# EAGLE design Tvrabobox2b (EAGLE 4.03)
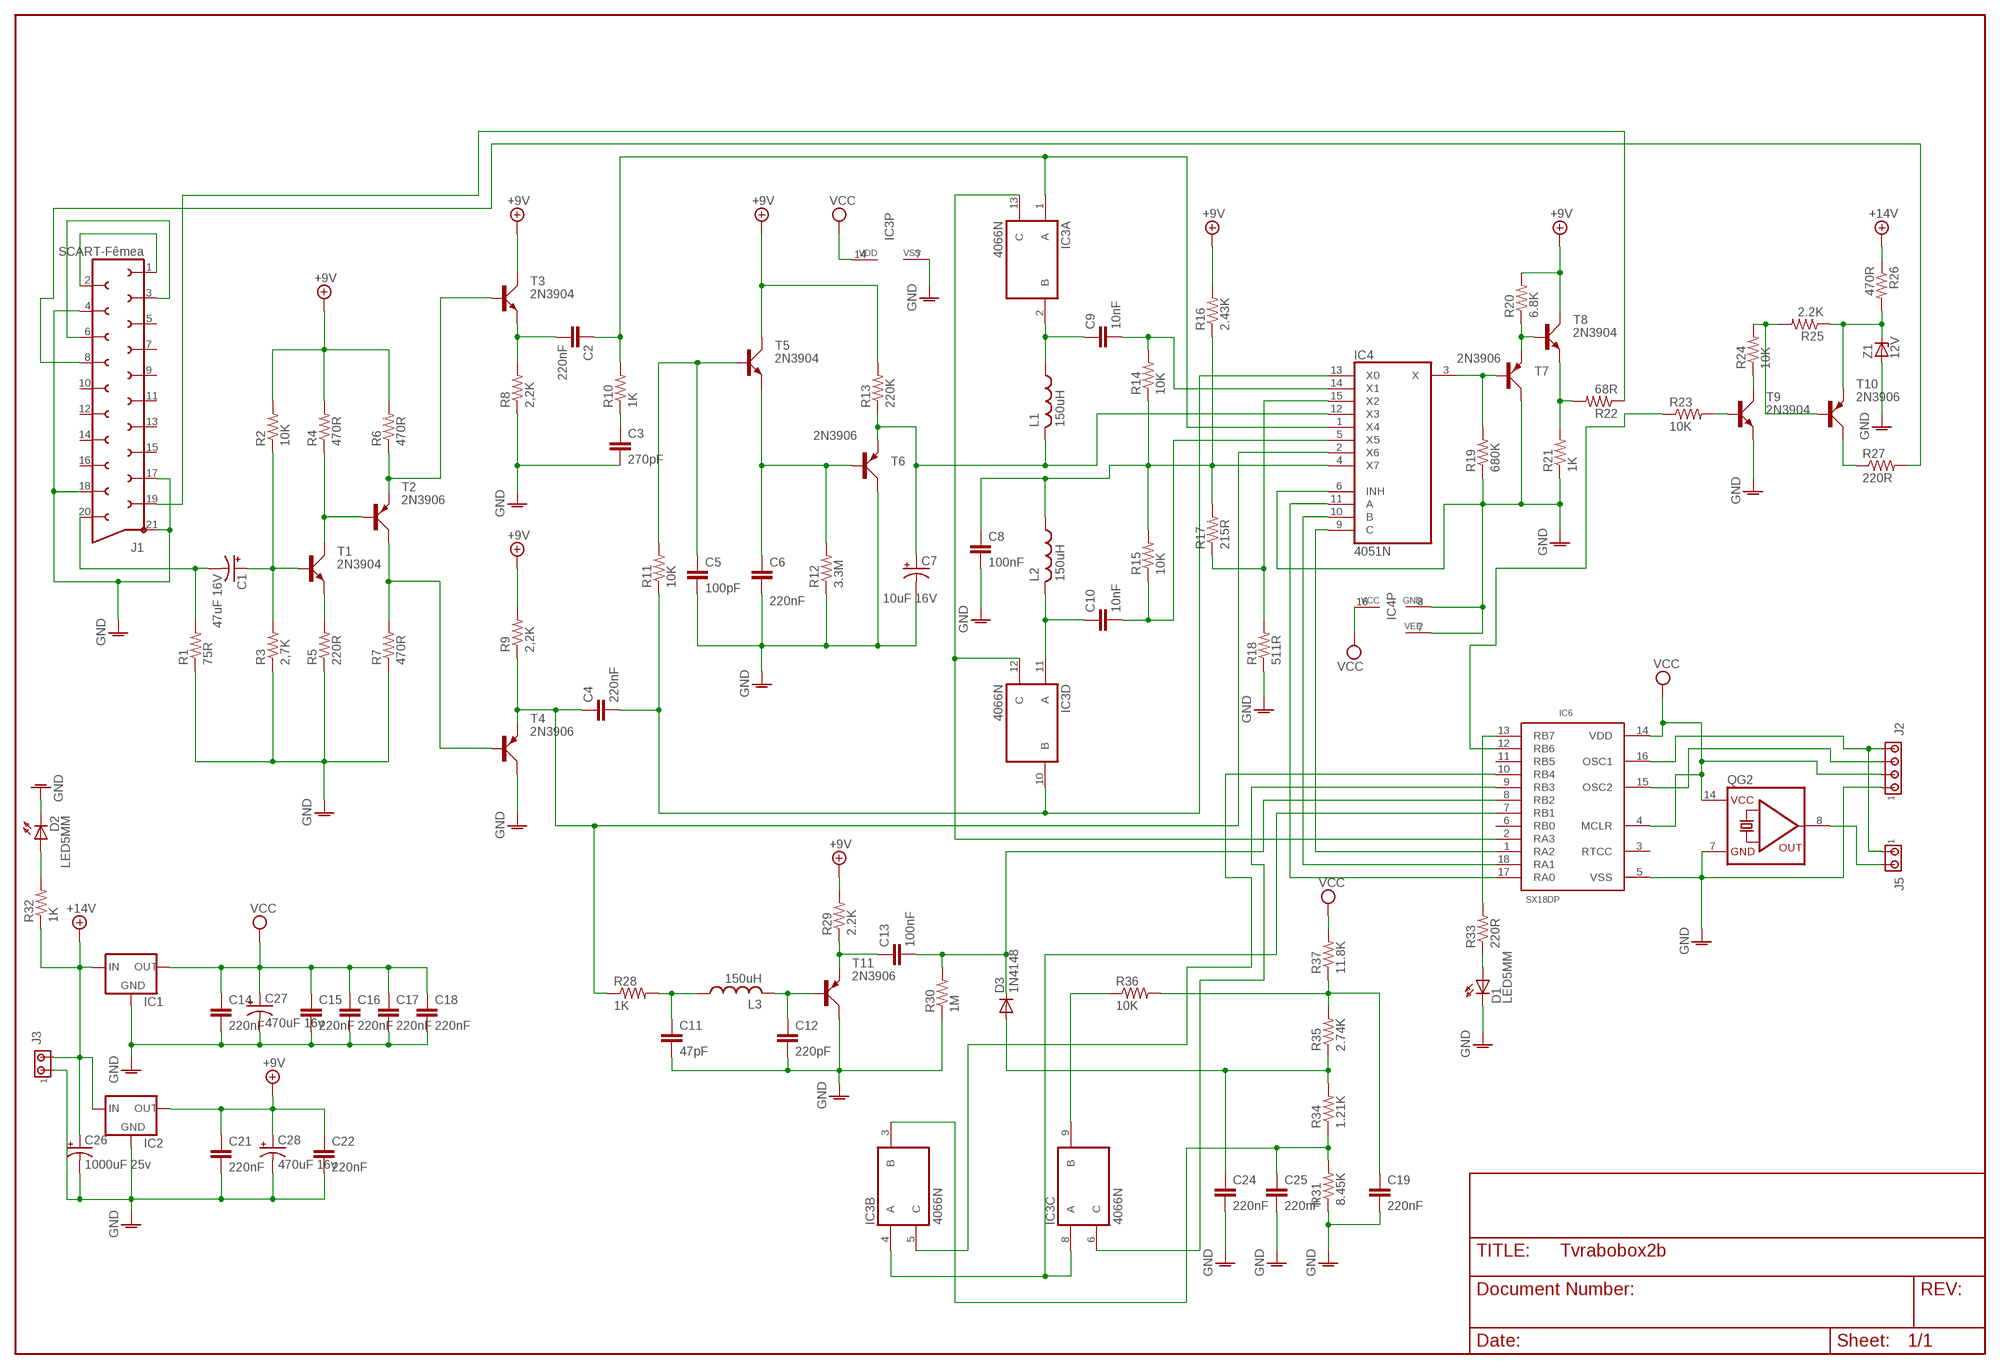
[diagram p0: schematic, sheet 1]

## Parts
C1  47uF 16V  CPOL-USTT2D5  [TT2D5]
C2  220nF  C-EU050-050X075  [C050-050X075]
C3  270pF  C-EU025-025X050  [C025-025X050]
C4  220nF  C-EU050-050X075  [C050-050X075]
C5  100pF  C-EU025-025X050  [C025-025X050]
C6  220nF  C-EU050-050X075  [C050-050X075]
C7  10uF 16V  CPOL-USTT2D5  [TT2D5]
C8  100nF  C-EU025-025X050  [C025-025X050]
C9  10nF  C-EU025-025X050  [C025-025X050]
C10  10nF  C-EU025-025X050  [C025-025X050]
C11  47pF  C-EU025-025X050  [C025-025X050]
C12  220pF  C-EU025-025X050  [C025-025X050]
C13  100nF  C-EU025-025X050  [C025-025X050]
C14  220nF  C-EU050-050X075  [C050-050X075]
C15  220nF  C-EU050-050X075  [C050-050X075]
C16  220nF  C-EU050-050X075  [C050-050X075]
C17  220nF  C-EU050-050X075  [C050-050X075]
C18  220nF  C-EU050-050X075  [C050-050X075]
C19  220nF  C-EU050-050X075  [C050-050X075]
C21  220nF  C-EU050-050X075  [C050-050X075]
C22  220nF  C-EU050-050X075  [C050-050X075]
C24  220nF  C-EU050-050X075  [C050-050X075]
C25  220nF  C-EU050-050X075  [C050-050X075]
C26  1000uF 25v  CPOL-USTT5D10  [TT5D10]
C27  470uF 16v  CPOL-USTT2D7  [TT2D7]
C28  470uF 16v  CPOL-USTT2D7  [TT2D7]
D1  LED5MM  [LED5MM]
D2  LED5MM  [LED5MM]
D3  1N4148  [DO35-10]
IC1  78XXS  [78XXS]
IC2  78XXS  [78XXS]
IC3  4066N  [DIL14]
IC4  4051N  [DIL16]
IC6  SX18AC/DP  [18DIP]
J1  SCART-Fêmea  SCART-F  [SCART-F]
J2  MTA04-100  [10X04MTA]
J3  MTA02-156  [1X2MTA]
J5  MTA02-100  [10X02MTA]
L1  150uH  L-US0207/10  [0207/10]
L2  150uH  L-US0207/10  [0207/10]
L3  150uH  L-US0207/10  [0207/10]
QG2  QG5860  [DIL14S]
R1  75R  R-US_0207/10  [0207/10]
R2  10K  R-US_0207/10  [0207/10]
R3  2,7K  R-US_0207/10  [0207/10]
R4  470R  R-US_0207/10  [0207/10]
R5  220R  R-US_0207/10  [0207/10]
R6  470R  R-US_0207/10  [0207/10]
R7  470R  R-US_0207/10  [0207/10]
R8  2,2K  R-US_0207/10  [0207/10]
R9  2,2K  R-US_0207/10  [0207/10]
R10  1K  R-US_0207/10  [0207/10]
R11  10K  R-US_0207/10  [0207/10]
R12  3.3M  R-US_0207/10  [0207/10]
R13  220K  R-US_0207/10  [0207/10]
R14  10K  R-US_0207/10  [0207/10]
R15  10K  R-US_0207/10  [0207/10]
R16  2.43K  R-US_0207/10  [0207/10]
R17  215R  R-US_0207/10  [0207/10]
R18  511R  R-US_0207/10  [0207/10]
R19  680K  R-US_0207/10  [0207/10]
R20  6.8K  R-US_0207/10  [0207/10]
R21  1K  R-US_0207/10  [0207/10]
R22  68R  R-US_0207/10  [0207/10]
R23  10K  R-US_0207/10  [0207/10]
R24  10K  R-US_0207/10  [0207/10]
R25  2.2K  R-US_0207/10  [0207/10]
R26  470R  R-US_0207/10  [0207/10]
R27  220R  R-US_0207/10  [0207/10]
R28  1K  R-US_0207/10  [0207/10]
R29  2.2K  R-US_0207/10  [0207/10]
R30  1M  R-US_0207/10  [0207/10]
R31  8.45K  R-US_0207/10  [0207/10]
R32  1K  R-US_0207/10  [0207/10]
R33  220R  R-US_0207/10  [0207/10]
R34  1.21K  R-US_0207/10  [0207/10]
R35  2.74K  R-US_0207/10  [0207/10]
R36  10K  R-US_0207/10  [0207/10]
R37  11.8K  R-US_0207/10  [0207/10]
T1  2N3904  [TO92D]
T2  2N3906  [TO92D]
T3  2N3904  [TO92D]
T4  2N3906  [TO92D]
T5  2N3904  [TO92D]
T6  2N3906  [TO92D]
T7  2N3906  [TO92D]
T8  2N3904  [TO92D]
T9  2N3904  [TO92D]
T10  2N3906  [TO92D]
T11  2N3906  [TO92D]
Z1  12V  BZX55  [DO35Z10]

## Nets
+9V: C21.2 C22.2 C28.+ IC2.OUT R2.2 R4.2 R6.2 R9.2 R13.2 R16.2 R20.2 R29.2 T3.C T5.C T8.C
+14V: C26.+ IC1.IN IC2.IN J3.2 R26.1 R32.1
GNDA: C3.1 C5.1 C6.1 C7.- C8.1 C11.1 C12.1 C14.1 C15.1 C16.1 C17.1 C18.1 C19.1 C21.1 C22.1 C24.1 C25.1 C26.- C27.- C28.- D1.K(C) D2.K(C) IC1.GND IC2.GND IC3.7(P:VSS) IC4.6(INH) IC4.7(VEE) IC4.8(GND) IC6.5(VSS) J1.4 J1.17 J1.18 J1.21 J2.4 J3.1 QG2.7(GND) R1.1 R3.1 R5.1 R7.1 R8.1 R12.1 R18.1 R19.1 R21.1 R30.1 R31.1 T4.C T6.C T7.C T9.E T11.C Z1.A ; supply symbol labelled GND
N$1: J1.1 J1.2
N$2: J1.3 J1.6
N$3: C4.1 IC3.10(D:B) IC4.13(X0) R11.1
N$4: C3.2 R10.1
N$5: R4.1 T1.C T2.B
N$6: R5.2 T1.E
N$7: C1.+ R2.1 R3.2 T1.B
N$8: C1.- J1.20 R1.2
N$9: C2.1 R8.2 T3.E
N$10: C4.2 IC4.2(X6) R9.1 R28.1 T4.E
N$11: C9.2 IC3.2(A:B) L1.2
N$12: C2.2 IC3.1(A:A) IC4.1(X4) R10.2
N$13: R6.1 T2.E T3.B
N$14: R7.2 T2.C T4.B
N$15: C5.2 R11.2 T5.B
N$16: C6.2 R12.2 T5.E T6.B
N$17: C8.2 IC4.4(X7) L2.2 R14.1 R15.2 R16.1 R17.2
N$18: IC4.15(X2) R17.1 R18.2
N$19: C7.+ IC4.12(X3) L1.1 R13.1 T6.E
N$20: C9.1 IC4.14(X1) R14.2
N$21: IC4.11(A) IC6.17(RA0)
N$22: C10.2 IC3.11(D:A) L2.1
N$23: IC4.10(B) IC6.18(RA1)
N$24: C10.1 IC4.5(X5) R15.1
N$25: IC4.9(C) IC6.1(RA2)
N$26: IC3.12(D:C) IC3.13(A:C) IC6.2(RA3)
N$27: IC4.3(X) R19.2 T7.B
N$28: R20.1 T7.E T8.B
N$29: J1.19 R22.1
N$30: R23.2 T9.B
N$31: R21.2 R22.2 T8.E
N$32: R24.1 T9.C
N$33: R24.2 R25.2 T10.B
N$34: C24.2 D3.A R34.2 R35.1
N$35: R27.1 T10.C
N$36: IC6.12(RB6) R23.1
N$37: J1.8 R27.2
N$38: R25.1 R26.2 T10.E Z1.C
N$39: IC3.9(C:B) R36.1
N$40: C25.2 IC3.3(B:B) R31.2 R34.1
N$41: IC3.6(C:C) IC6.9(RB3)
N$42: C11.2 L3.2 R28.2
N$43: C12.2 L3.1 T11.B
N$44: C13.2 R29.1 T11.E
N$45: IC3.5(B:C) IC6.10(RB4)
N$46: C13.1 D3.C IC6.8(RB2) R30.2
N$47: D2.A R32.2
N$48: IC3.4(B:A) IC3.8(C:A) IC6.7(RB1)
N$49: C19.2 R35.2 R36.2 R37.1
N$52: IC6.15(OSC2) J2.2
N$53: IC6.16(OSC1) J2.1 J5.1
N$55: J5.2 QG2.8(OUT)
N$63: D1.A R33.1
N$64: IC6.13(RB7) R33.2
VCC: C14.2 C15.2 C16.2 C17.2 C18.2 C27.+ IC1.OUT IC3.14(P:VDD) IC4.16(VCC) IC6.4(MCLR) IC6.14(VDD) J2.3 QG2.14(VCC) R37.2
Unconnected: IC6.3(RTCC) IC6.6(RB0) IC6.11(RB5) J1.5 J1.7 J1.9 J1.10 J1.11 J1.12 J1.13 J1.14 J1.15 J1.16

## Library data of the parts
C1 C7 C26-C28 = rcl:CPOL-US: POLARIZED CAPACITOR, American symbol
C2-C6 C8-C19 C21 C22 C24 C25 = rcl:C-EU: CAPACITOR, European symbol
D1 D2 = led:LED5MM: LED
D3 = diode:1N4148: DIODE
IC1 IC2 = v-reg:78XXS: VOLTAGE REGULATOR
IC3 = 40xx:4066: Quad bilateral ANALOG SWITCH
IC4 = 40xx:4051: 8-channel ANALOG MULTIPLEXER
IC6 = ubicom_v2:SX18AC/DP
J1 = con-hirschmann:SCART-F: TV SCART CONNECTOR
J2 = con-amp:MTA04-100: AMP CONNECTOR
J3 = con-amp:MTA02-156: AMP CONNECTOR
J5 = con-amp:MTA02-100: AMP CONNECTOR
L1-L3 = rcl:L-US: INDUCTOR, American symbol
QG2 = crystal:QG5860: CRYSTAL RESONATOR
R1-R37 = rcl:R-US_: RESISTOR, American symbol
T1 T3 T5 T8 T9 = transistor-small-signal:2N3904: NPN TRANSISTOR
T2 T4 T6 T7 T10 T11 = transistor-small-signal:2N3906: PNP TRANSISTOR
Z1 = diode:BZX55: Z DIODE

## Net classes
0 default: width 0.4 mm

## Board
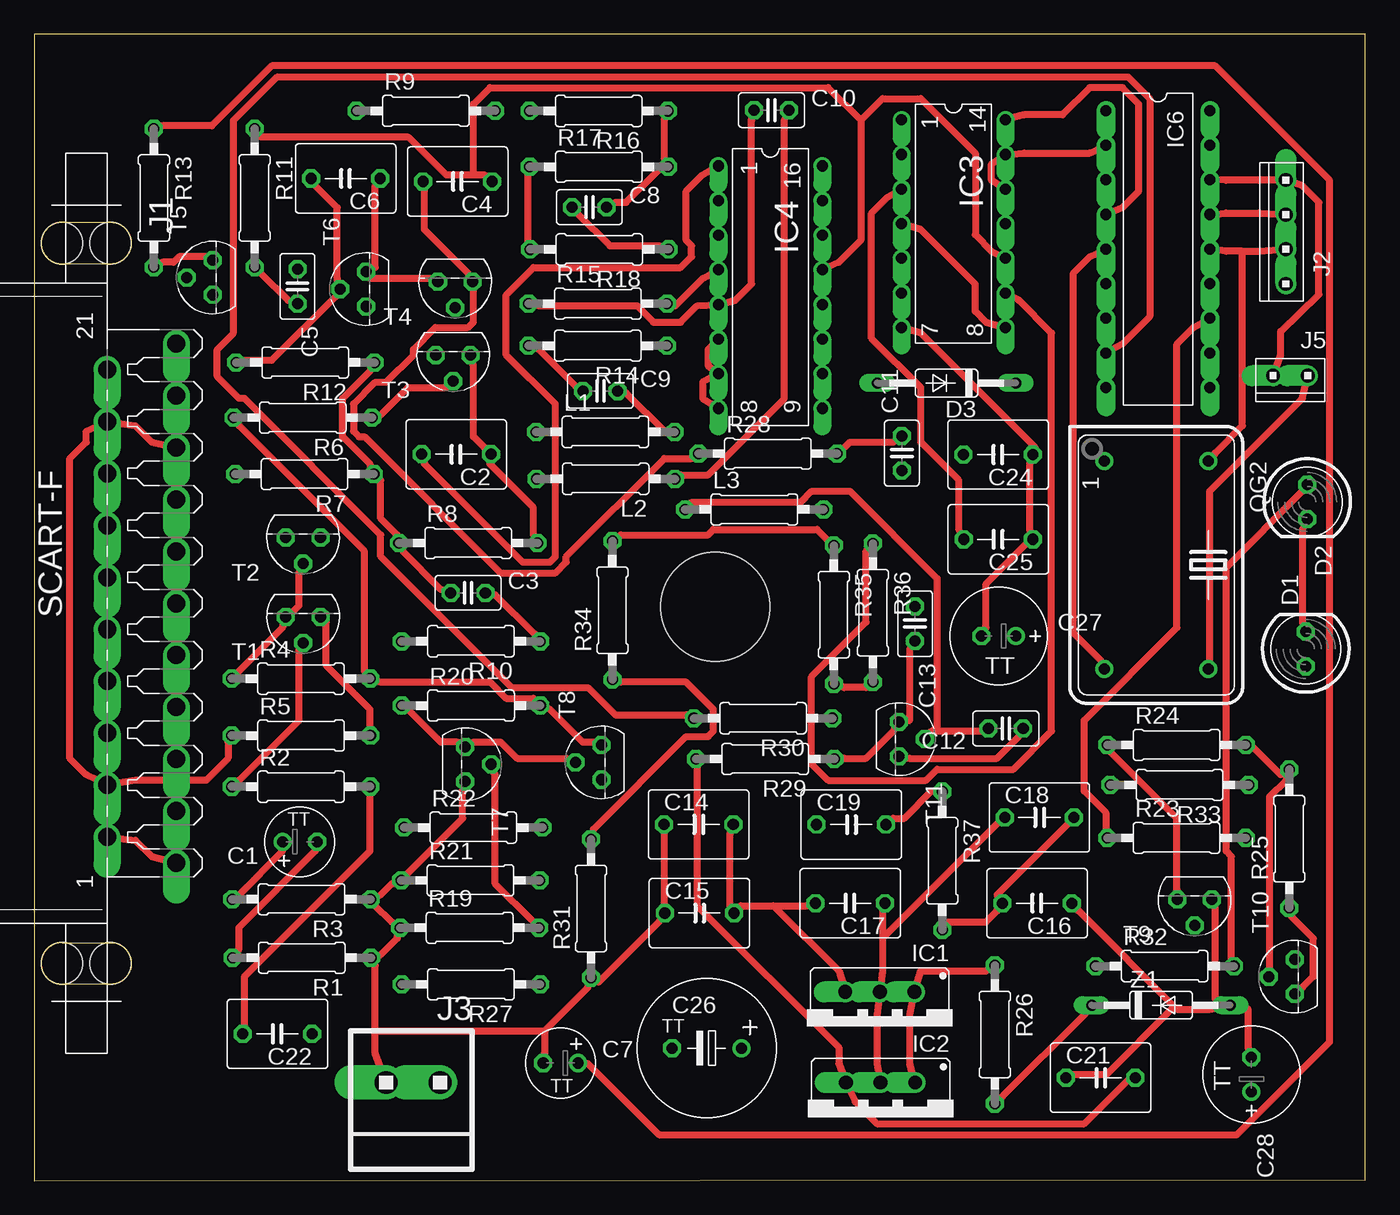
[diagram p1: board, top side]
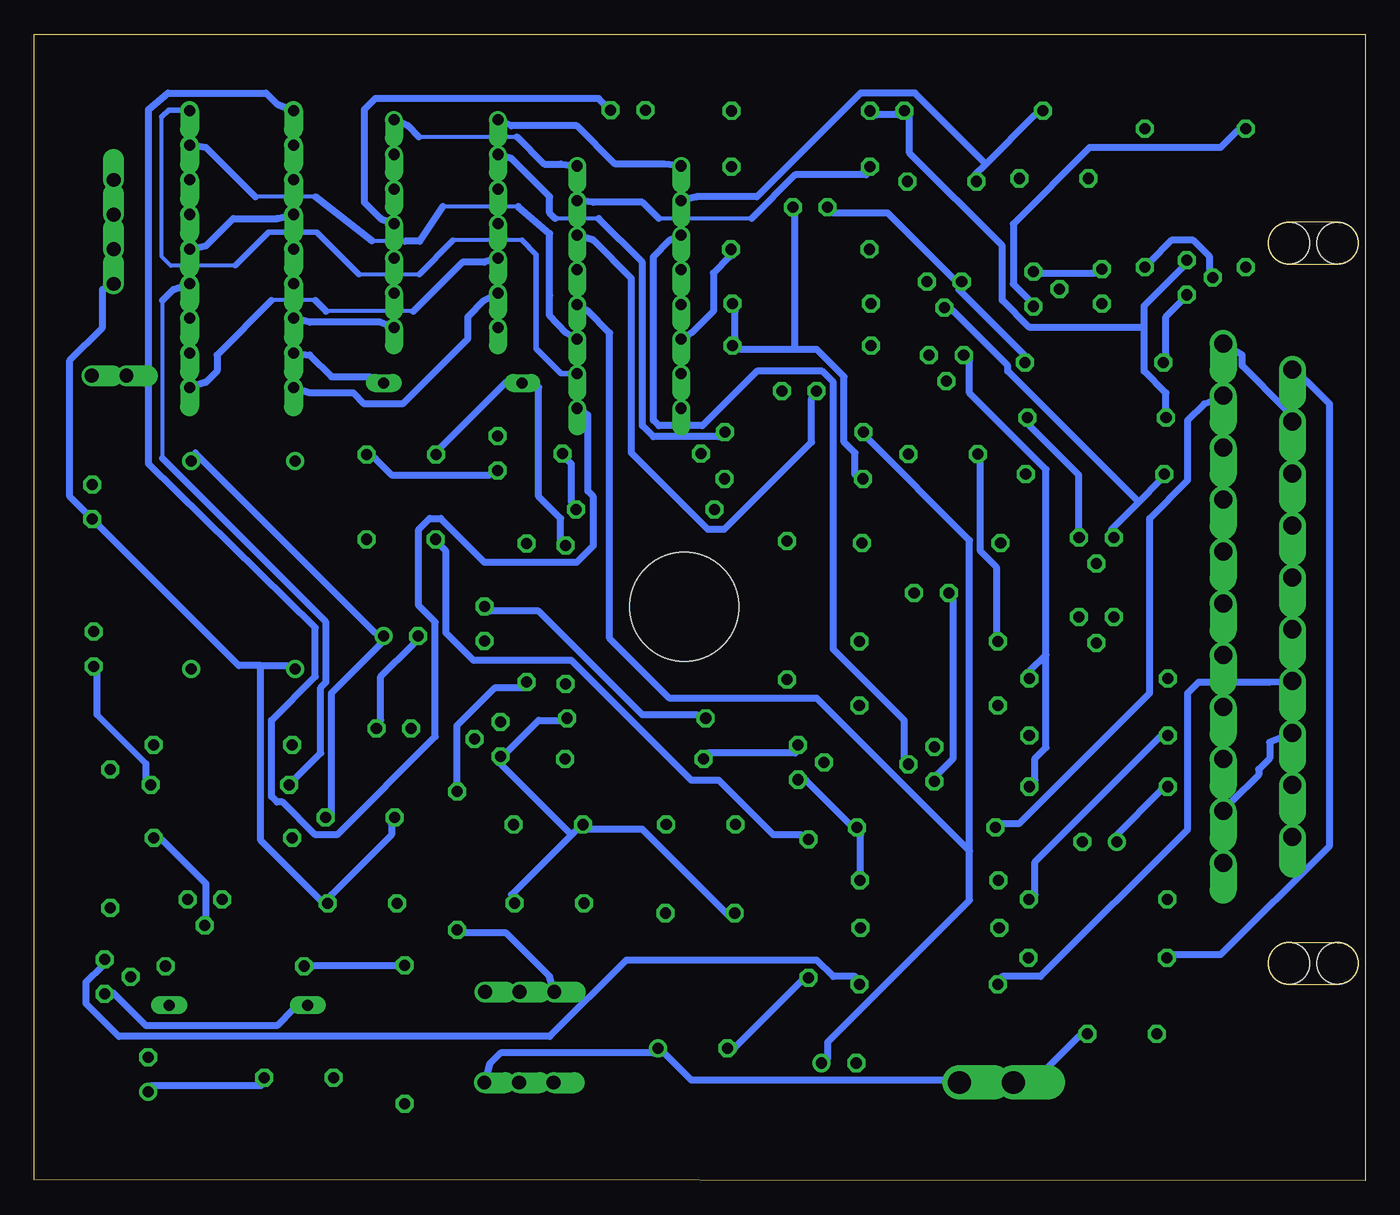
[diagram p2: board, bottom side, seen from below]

Size 97.65 x 84.11 mm. Coordinates in mm from the lower left corner, seen from the top.
Outline: 0,0 97.65,0.06 97.65,84.11 0,84.11 0,0
Copper layers used: Top, Bottom
Holes 8 mm at 49.98,42.12

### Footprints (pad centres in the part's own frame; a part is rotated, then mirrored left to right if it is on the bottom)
TT2D5 = drill 0.813 round: + 1.27,0 | drill 0.813 octagon: - -1.27,0
C050-050X075 = drill 0.813 octagon: 1 -2.54,0; 2 2.54,0
C025-025X050 = drill 0.813 octagon: 1 -1.27,0; 2 1.27,0
TT5D10 = drill 0.813 round: + 2.54,0 | drill 0.813 octagon: - -2.54,0
TT2D7 = drill 0.813 round: + 1.27,0 | drill 0.813 octagon: - -1.27,0
LED5MM = drill 0.813 octagon: A -1.27,0; K 1.27,0
DO35-10 = drill 0.813 long: A 5.08,0; C -5.08,0
78XXS = drill 1.016 offset: GND 0,-2.54; IN -2.54,-2.54; OUT 2.54,-2.54
DIL14 = drill 0.813 offset: 1 -7.62,-3.81; 2 -5.08,-3.81; 3 -2.54,-3.81; 4 0,-3.81; 5 2.54,-3.81; 6 5.08,-3.81; 7 7.62,-3.81; 8 7.62,3.81; 9 5.08,3.81; 10 2.54,3.81; 11 0,3.81; 12 -2.54,3.81; 13 -5.08,3.81; 14 -7.62,3.81
DIL16 = drill 0.813 offset: 1 -8.89,-3.81; 2 -6.35,-3.81; 3 -3.81,-3.81; 4 -1.27,-3.81; 5 1.27,-3.81; 6 3.81,-3.81; 7 6.35,-3.81; 8 8.89,-3.81; 9 8.89,3.81; 10 6.35,3.81; 11 3.81,3.81; 12 1.27,3.81; 13 -1.27,3.81; 14 -3.81,3.81; 15 -6.35,3.81; 16 -8.89,3.81
18DIP = drill 0.813 pad 1.397 offset: 1 -16.192,-3.81; 2 -13.652,-3.81; 3 -11.113,-3.81; 4 -8.572,-3.81; 5 -6.032,-3.81; 6 -3.493,-3.81; 7 -0.953,-3.81; 8 1.587,-3.81; 9 4.128,-3.81; 10 4.128,3.81; 11 1.587,3.81; 12 -0.953,3.81; 13 -3.493,3.81; 14 -6.032,3.81; 15 -8.572,3.81; 16 -11.113,3.81; 17 -13.652,3.81; 18 -16.192,3.81
SCART-F = drill 1.321 offset: 1 19.05,5.08; 2 17.145,0; 3 15.24,5.08; 4 13.335,0; 5 11.43,5.08; 6 9.525,0; 7 7.62,5.08; 8 5.715,0; 9 3.81,5.08; 10 1.905,0; 11 0,5.08; 12 -1.905,0; 13 -3.81,5.08; 14 -5.715,0; 15 -7.62,5.08; 16 -9.525,0; 17 -11.43,5.08; 18 -13.335,0; 19 -15.24,5.08; 20 -17.145,0; 21 -19.05,5.08 | hole 3.023: 26.416,0.254; 26.416,-3.302; -26.416,0.254; -26.416,-3.302
10X04MTA = drill 1.016 offset: 1 3.81,0; 2 1.27,0; 3 -1.27,0; 4 -3.81,0
1X2MTA = drill 1.676 offset: 1 1.981,0; 2 -1.981,0
10X02MTA = drill 1.016 offset: 1 1.27,0; 2 -1.27,0
0207/10 = drill 0.813 octagon: 1 -5.08,0; 2 5.08,0
DIL14S = drill 0.813 round: 1 -7.62,-3.81; 7 7.62,-3.81; 8 7.62,3.81; 14 -7.62,3.81
TO92D = drill 0.813 octagon: B 0,1.905; C 1.27,0; E -1.27,0
DO35Z10 = drill 0.813 long: A 5.08,0; C -5.08,0

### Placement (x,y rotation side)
C1  19.49,24.87 180 top
C2  30.97,53.29 180 top
C3  31.83,43.13 0 top
C4  31.06,73.3 180 top
C5  19.32,65.61 270 top
C6  22.85,73.53 180 top
C7  38.62,8.64 0 top
C8  40.73,71.41 0 top
C9  41.53,57.94 0 top
C10  54.08,78.53 0 top
C11  63.65,53.37 90 top
C12  71.27,33.18 180 top
C13  64.61,40.87 270 top
C14  48.74,26.14 0 top
C15  48.8,19.64 0 top
C16  73.57,20.36 180 top
C17  59.87,20.37 180 top
C18  73.74,26.65 0 top
C19  59.94,26.13 0 top
C21  78.22,7.57 0 top
C22  17.85,10.78 180 top
C24  70.71,53.27 180 top
C25  70.72,47.05 180 top
C26  49.33,9.73 0 top
C27  70.76,39.96 0 top
C28  89.29,7.8 270 top
D1  93.28,39.01 90 top
D2  93.38,49.8 270 top
D3  66.93,58.51 180 top
IC1  62.03,11.31 180 top
IC2  62.08,4.66 180 top
IC3  67.43,70.2 270 top
IC4  54.01,65.55 270 top
IC6  82.43,62.31 270 top
J1  5.36,42.36 270 top
J2  91.82,69.6 90 top
J3  27.79,7.21 180 top
J5  92.14,59.06 180 top
L1  41.91,54.94 0 top
L2  41.93,51.49 180 top
L3  52.83,49.25 0 top
QG2  82.31,45.17 270 top
R1  19.63,16.36 180 top
R2  19.58,28.91 0 top
R3  19.62,20.65 180 top
R4  19.57,36.83 0 top
R5  19.58,32.66 0 top
R6  19.7,55.98 180 top
R7  19.84,51.84 180 top
R8  31.84,46.78 0 top
R9  28.73,78.48 0 top
R10  32.04,39.58 180 top
R11  16.18,72.09 270 top
R12  19.89,60.03 180 top
R13  8.79,72.09 270 top
R14  41.34,61.26 180 top
R15  41.36,64.34 0 top
R16  41.41,78.48 180 top
R17  41.43,74.38 0 top
R18  41.46,68.32 180 top
R19  31.94,18.56 0 top
R20  32.05,34.86 0 top
R21  32.01,22.04 0 top
R22  32.21,25.91 0 top
R23  83.79,25.15 0 top
R24  83.8,31.98 0 top
R25  92.06,25.09 90 top
R26  70.47,10.74 270 top
R27  32.05,14.41 180 top
R28  53.82,53.34 0 top
R29  53.62,30.94 180 top
R30  53.47,33.93 180 top
R31  40.85,19.97 90 top
R32  82.93,15.75 0 top
R33  84.01,29.04 180 top
R34  42.42,41.85 90 top
R35  58.66,41.53 270 top
R36  61.52,41.67 270 top
R37  66.61,23.47 270 top
T1  19.74,41.36 180 top
T2  19.73,47.18 180 top
T3  30.73,60.56 180 top
T4  30.88,65.94 180 top
T5  13.1,66.26 90 top
T6  24.34,65.41 90 top
T7  31.62,30.56 270 top
T8  41.61,30.69 90 top
T9  85.13,20.64 180 top
T10  92.48,14.97 90 top
T11  63.44,32.4 270 top
Z1  82.66,12.89 0 top

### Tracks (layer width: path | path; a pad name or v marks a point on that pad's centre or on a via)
+9V
  Top 0.508: R13.2 9.43,67.38 10.23,67.38 10.63,67.78 12.63,67.78 T5.C | C21.2 80.23,7.38 77.03,4.18 61.83,4.18 60.23,5.78 IC2.OUT 59.03,8.58 59.03,9.78 48.63,20.18 48.63,30.18 R29.2 | C22.2 15.43,11.38 15.43,14.98 24.63,24.18 24.63,28.18 R2.2 | T8.C 41.03,32.18 40.23,32.18 37.83,34.58 R20.2 36.63,35.38 34.63,35.38 33.43,36.58 25.43,36.58 R4.2 24.23,37.38 24.23,46.18 15.03,55.38 R6.2
  Bottom 0.508: R16.2 35.83,78.18 34.23,78.18 R9.2 33.43,78.18 33.43,75.38 26.63,68.58 26.63,64.58 24.63,62.58 16.23,62.58 | 16.23,62.58 16.23,64.18 13.43,66.98 T5.C | 16.23,62.58 16.23,59.38 14.63,57.78 14.63,56.58 R6.2 | C21.2 81.03,6.98 89.03,6.98 C28.+ | 23.43,38.58 23.43,52.18 29.03,57.78 29.03,60.18 T3.C | 23.43,38.58 24.63,37.38 R4.2 | R29.2 48.23,31.38 41.83,31.38 T8.C | 23.43,38.58 23.43,31.78 24.23,30.98 24.23,29.38 R2.2
+14V
  Top 0.508: R26.1 69.83,15.38 65.03,15.38 IC1.IN 64.23,12.18 64.23,8.58 IC2.IN
  Bottom 0.508: R32.1 77.43,15.78 71.03,15.78 R26.1 | IC2.IN 64.23,8.58 63.43,9.38 52.23,9.38 C26.+ 51.43,9.38 49.43,7.38 30.63,7.38 J3.2
GNDA
  Top 0.508: IC6.5 77.43,67.78 76.23,66.58 76.23,40.18 78.23,38.18 QG2.7 | D1.K 93.03,40.98 93.03,47.78 D2.K | 83.83,12.58 86.23,12.58 Z1.A | 83.83,12.58 83.43,12.58 78.63,7.78 76.23,7.78 C21.1 | C28.- 89.03,9.78 89.03,12.58 Z1.A | T9.E 86.63,20.18 86.63,13.38 Z1.A | 83.83,12.58 76.63,19.78 C16.1 | 62.23,17.78 62.23,15.38 IC1.GND 61.83,12.18 61.83,8.58 IC2.GND | 62.23,17.78 62.23,19.78 C17.1 | IC3.7 65.03,62.18 73.43,53.78 C24.1 73.03,52.58 73.03,47.78 C25.1 72.63,46.58 69.83,43.78 69.83,40.58 C27.- | T11.C 64.23,30.98 70.63,30.98 72.23,32.58 C12.1 | 62.23,17.78 70.63,26.18 C18.1 | C6.1 25.03,72.98 25.03,66.98 T6.C 24.63,66.18 29.03,66.18 T4.C | IC4.8 49.03,57.38 49.03,58.58 IC4.7 49.43,59.78 49.43,60.98 IC4.6 | R18.1 45.83,68.58 42.23,68.58 39.83,70.98 C8.1 | C14.1 46.23,25.38 46.23,20.18 C15.1 45.83,18.98 41.43,14.58 R31.1 40.63,14.18 37.43,10.98 | 37.43,10.98 37.43,9.38 C7.- | C3.1 29.83,43.38 27.03,46.18 R8.1 26.63,47.38 25.43,48.58 25.43,51.38 R7.1 24.63,52.58 22.63,54.58 22.63,57.38 24.63,59.38 R12.1 | J1.17 8.63,54.18 7.43,55.38 J1.18 3.83,54.98 3.83,54.18 2.63,52.98 2.63,30.98 3.83,29.78 J1.4 7.43,29.38 12.63,29.38 14.23,30.98 14.23,32.18 R5.1 | T7.C 31.43,28.58 31.43,26.58 27.43,22.58 R21.1 26.23,21.78 25.43,20.98 R3.1 25.03,20.18 26.23,18.98 R19.1 26.63,17.78 25.43,16.58 R1.1 25.03,15.78 25.03,10.98 | 25.03,10.98 25.03,9.38 J3.1 | 25.03,10.98 37.43,10.98
  Bottom 0.508: 81.03,37.78 82.63,37.78 93.03,48.18 D2.K 93.83,48.98 95.03,50.18 95.03,60.18 92.63,62.58 92.63,65.38 J2.4 | 81.03,37.78 79.03,37.78 QG2.7 | C18.1 71.43,26.18 71.43,25.38 75.83,20.98 C16.1 76.63,20.58 81.03,24.98 81.03,37.78 | 58.23,25.38 62.63,20.98 C17.1 | 58.23,25.38 57.83,25.78 C19.1 57.03,25.78 53.03,25.78 46.63,19.38 C15.1 | 58.23,25.38 63.43,30.58 T11.C 63.03,31.38 60.63,33.78 59.03,33.78 R30.1 | C12.1 72.23,33.78 72.23,36.98 69.83,39.38 C27.- | C11.1 64.23,51.78 71.43,51.78 72.63,52.98 C24.1 | R12.1 25.03,60.58 29.83,65.38 T4.C 30.23,66.18 35.03,70.98 39.03,70.98 C8.1 | C5.1 19.83,66.58 23.83,66.58 T6.C | IC4.6 49.43,62.18 47.83,63.78 47.83,66.58 46.63,67.78 R18.1 | C26.- 46.23,9.78 41.43,14.58 R31.1 | J1.21 9.03,60.58 9.03,59.78 5.83,56.58 J1.18 | C22.1 21.03,10.58 24.63,6.98 J3.1 | R5.1 15.03,32.58 24.23,23.38 24.23,20.98 R3.1 | C3.1 30.23,42.58 30.23,30.98 31.43,29.78 T7.C
N$1
  Top 0.508: J1.2 7.43,24.98 8.63,23.78 J1.1
N$2
  Bottom 0.508: J1.6 7.03,32.18 7.03,30.98 7.83,30.18 7.83,29.78 9.83,27.78 J1.3
N$3
  Top 0.508: 32.23,73.78 30.23,73.78 27.43,76.58 16.63,76.58 R11.1 | 32.23,73.78 33.03,73.78 C4.1 | 60.63,77.78 60.63,68.98 59.03,67.38 IC4.13 | 60.63,77.78 62.23,79.38 65.03,79.38 69.03,75.38 69.03,69.38 70.23,68.18 IC3.10 | 32.23,73.78 32.23,78.98 33.43,80.18 58.23,80.18 60.63,77.78
N$4
  Top 0.508: C3.2 33.83,42.98 36.63,40.18 R10.1
N$5
  Top 0.508: R4.1 15.03,37.38 18.23,40.58 T1.C 19.03,41.78 19.43,42.18 19.43,44.58 T2.B
N$6
  Top 0.508: R5.2 24.63,33.38 24.63,34.58 21.43,37.78 21.43,40.98 T1.E
N$7
  Top 0.508: R3.2 15.03,20.98 18.23,24.18 C1.+ | T1.B 19.43,38.98 19.43,33.78 15.03,29.38 R2.1
  Bottom 0.508: R2.1 15.03,28.58 18.23,25.38 C1.+
N$8
  Top 0.508: R1.2 15.03,16.98 15.03,18.58 20.63,24.18 C1.-
  Bottom 0.508: J1.20 4.23,58.58 2.63,56.98 2.63,24.58 10.63,16.58 14.23,16.58 R1.2
N$9
  Top 0.508: R8.2 36.63,47.38 36.63,49.38 33.43,52.58 C2.1 33.03,53.78 32.23,54.58 32.23,59.78 T3.E
N$10
  Top 0.508: R28.1 48.23,52.98 46.23,52.98 39.03,45.78 39.03,45.38 38.23,44.58 34.23,44.58 24.23,54.58 23.83,54.58 23.43,54.98 23.43,56.98 25.03,58.58 25.83,58.58 27.83,60.58 27.83,60.98 29.43,62.58 31.83,62.58 32.23,62.98 32.23,65.38 T4.E 31.83,66.58 28.63,69.78 28.63,72.58 C4.2
  Bottom 0.508: 27.83,74.58 28.63,73.78 C4.2 | 27.83,74.58 24.23,78.18 R9.1 | 27.83,74.58 33.03,79.78 37.03,79.78 44.63,72.18 49.03,72.18 IC4.2
N$11
  Top 0.508: C9.2 43.43,57.78 46.23,54.98 L1.2
  Bottom 0.305: 56.23,70.58 59.43,70.58
  Bottom 0.508: 59.43,70.58 59.83,70.98 59.83,72.18 62.63,74.98 IC3.2 | 56.23,70.58 53.03,67.38 53.03,55.38 52.23,54.58 47.43,54.58 L1.2
N$12
  Top 0.508: C2.2 28.63,52.58 35.83,45.38 37.83,45.38 38.23,45.78 38.23,56.98 34.63,60.58 34.63,64.98 36.63,66.98 47.43,66.98 48.23,67.78 48.23,68.58 47.83,68.98 47.83,72.58 49.03,73.78 IC4.1
  Bottom 0.508: R10.2 27.03,40.18 27.03,44.98 28.23,46.18 28.23,52.98 C2.2 | IC4.1 51.43,74.58 55.03,74.58 57.83,77.38 62.63,77.38 IC3.1
N$13
  Top 0.508: T3.B 30.23,58.18 27.43,58.18 25.43,56.18 R6.1
  Bottom 0.508: T2.E 21.03,47.78 21.03,51.78 24.63,55.38 R6.1
N$14
  Bottom 0.508: 16.63,49.78 18.63,47.78 T2.C | 16.63,49.78 15.03,51.38 R7.2 | 16.63,49.78 26.23,59.38 26.23,59.78 30.23,63.78 T4.B
N$15
  Top 0.508: C5.2 18.63,64.58 16.63,66.58 R11.2
  Bottom 0.508: T5.B 11.43,66.58 11.43,67.78 12.63,68.98 14.23,68.98 15.83,67.38 R11.2
N$16
  Top 0.508: C6.2 20.63,72.98 22.23,71.38 22.23,66.18 T6.B 22.23,64.98 17.43,60.18 15.43,60.18 R12.2
  Bottom 0.508: R12.2 14.63,60.58 14.63,63.38 13.43,64.58 T5.E
N$17
  Top 0.508: C8.2 42.63,71.78 43.43,71.78 45.83,74.18 R17.2 46.23,74.98 46.23,77.78 R16.1 | IC4.4 49.03,66.18 47.03,64.18 R15.2
  Bottom 0.508: 41.83,60.98 45.83,60.98 R14.1 46.23,61.78 46.23,63.78 R15.2 | 41.83,60.98 40.23,60.98 38.23,58.98 38.23,54.18 37.43,53.38 37.43,51.78 L2.2 | 41.83,60.98 41.83,70.98 C8.2
N$18
  Top 0.508: R18.2 36.23,68.98 36.23,73.78 R17.1
  Bottom 0.305: 45.03,70.58 51.83,70.58
  Bottom 0.508: 51.83,70.58 53.03,71.78 56.63,71.78 IC4.15 | 45.03,70.58 41.83,73.78 36.63,73.78 R17.1
N$19
  Top 0.508: R13.1 9.43,77.38 13.03,77.38 17.43,81.78 86.63,81.78 95.03,73.38 95.03,10.18 88.23,3.38 45.83,3.38 40.63,8.58 C7.+
  Bottom 0.508: T6.E 24.63,64.58 25.83,65.78 25.83,70.18 20.23,75.78 10.63,75.78 9.43,76.98 R13.1 | 29.03,24.18 29.03,46.98 36.63,54.58 L1.1 | 29.03,24.18 29.03,20.58 39.43,10.18 39.43,8.98 C7.+ | 29.03,24.18 40.23,35.38 51.03,35.38 55.43,39.78 55.43,62.18 57.03,63.78 IC4.12
N$20
  Top 0.508: R14.2 37.03,60.98 39.83,58.18 C9.1
  Bottom 0.508: IC4.14 56.63,68.98 53.83,66.18 53.83,53.38 48.23,47.78 47.03,47.78 40.63,54.18 40.63,57.38 C9.1
N$21
  Bottom 0.305: 62.14,71.46 67.67,71.46 | 70.45,68.92 72.87,68.93 | 77.03,72.18 81.43,72.18
  Bottom 0.508: 62.14,71.46 59.84,69.48 59.84,64.95 59.84,63.45 58.63,62.18 IC4.11 | 67.67,71.46 69.37,68.92 70.45,68.92 | 72.87,68.93 77.03,72.18 | 81.43,72.18 85.03,75.78 IC6.17
N$22
  Top 0.508: L2.1 47.43,51.78 49.43,51.78 55.03,57.38 55.03,77.78 C10.2
  Bottom 0.508: IC3.11 72.23,70.58 73.43,71.78 73.43,78.58 72.63,79.38 56.23,79.38 55.83,78.98 C10.2
N$23
  Bottom 0.305: 61.86,68.99 66.9,68.99 | 69.43,66.47 73.81,66.47 | 82.91,67.13 87.63,67.13 88.28,67.79 88.28,78.04 | 86.24,78.52 IC6.18
  Bottom 0.406: IC4.10 58.98,59.2 60.82,61.04 60.82,67.95 61.86,68.99 | 66.9,68.99 69.43,66.47 | 73.81,66.47 76.94,69.6 80.44,69.6 82.91,67.13 | 88.28,78.04 87.79,78.53 86.25,78.53 86.24,78.52
N$24
  Top 0.508: C10.1 52.63,77.78 52.63,65.78 51.43,64.58 IC4.5 48.63,64.18 47.43,62.98 45.43,62.98 44.23,64.18 37.03,64.18 R15.1
N$25
  Bottom 0.508: IC4.9 57.03,56.18 57.03,50.58 56.63,50.18 56.63,46.58 57.83,45.38 64.63,45.38 67.83,48.58 68.63,48.58 69.43,47.78 69.43,42.18 68.23,40.98 68.23,32.58 75.43,25.38 77.03,25.38 79.43,27.78 79.83,27.78 80.23,28.18 80.23,33.78 77.03,36.98 77.03,40.58 89.26,52.58 89.26,78.58 87.83,79.78 80.63,79.78 79.83,78.98 IC6.1
N$26
  Top 0.508: IC3.12 70.23,73.38 70.23,74.58 IC3.13 72.63,75.38 77.43,75.38 IC6.2
N$27
  Top 0.508: T7.B 33.83,29.78 33.83,21.78 36.63,18.98 R19.2
  Bottom 0.508: IC4.3 51.03,68.98 52.23,67.78 52.23,55.78 51.83,55.38 48.63,55.38 44.63,59.38 39.83,59.38 39.03,58.58 39.03,38.98 33.83,33.78 33.83,30.98 T7.B
N$28
  Top 0.508: R20.1 27.43,34.58 29.83,32.18 31.03,32.18 T7.E 32.23,32.18 34.23,32.18 35.43,30.98 39.03,30.98 T8.B
N$29
  Bottom 0.508: R22.1 26.63,26.18 25.43,26.18 15.83,35.78 15.83,48.58 13.03,51.38 13.03,55.78 11.83,56.98 J1.19
N$30
  Bottom 0.508: T9.B 85.03,19.38 85.03,21.78 88.23,24.98 R23.2
N$31
  Bottom 0.508: R21.2 37.03,22.58 37.03,25.38 R22.2 37.83,26.18 41.03,29.38 T8.E
N$32
  Top 0.508: T9.C 83.83,21.38 83.83,26.58 79.03,31.38 R24.1
N$33
  Top 0.508: T10.B 90.63,15.38 90.63,28.18 91.83,29.38 R25.2 91.43,29.78 89.43,31.78 R24.2
N$34
  Top 0.508: R34.2 43.03,47.38 49.43,47.38 49.83,47.78 57.43,47.78 58.23,46.98 R35.1
  Bottom 0.508: R35.1 59.03,46.98 59.03,48.58 60.63,50.18 60.63,58.18 D3.A 63.03,58.58 67.83,53.78 C24.2
N$35
  Bottom 0.508: R27.1 37.43,14.98 39.03,14.98 40.23,16.18 54.23,16.18 59.83,10.58 91.43,10.58 93.83,12.98 93.83,14.58 92.63,15.78 T10.C
N$36
  Top 0.508: R23.1 78.63,25.78 78.63,26.98 77.03,28.58 77.03,33.78 83.83,40.58 83.83,61.38 85.03,62.58 IC6.12
N$37
  Bottom 0.508: R27.2 26.63,14.98 23.83,14.98 13.03,25.78 13.03,35.78 12.23,36.58 7.03,36.58 J1.8
N$38
  Top 0.508: T10.E 93.03,14.18 93.83,14.98 93.83,17.78 92.23,19.38 R25.1 | R26.2 71.03,6.18 77.03,12.18 Z1.C
  Bottom 0.508: T10.E 91.83,13.78 89.43,11.38 79.83,11.38 78.63,12.58 Z1.C
N$39
  Top 0.508: R36.1 61.03,46.18 61.03,40.98 57.03,36.98 57.03,30.58 58.23,29.38 65.43,29.38 66.23,30.18 71.83,30.18 74.63,32.98 74.63,62.18 72.23,64.58 IC3.9
N$40
  Top 0.508: R31.2 41.03,25.78 47.83,32.58 49.43,32.58 49.83,32.98 49.83,34.58 47.83,36.58 43.03,36.58 R34.1 | C25.2 67.83,47.78 67.83,51.38 65.03,54.18 65.03,58.18 61.43,61.78 61.43,70.98 62.63,72.18 IC3.3
  Bottom 0.508: R31.2 41.43,25.38 43.43,25.38 47.43,29.38 49.43,29.38 58.23,38.18 65.43,38.18 67.43,40.18 67.43,46.18 67.83,46.58 C25.2
N$41
  Bottom 0.508: IC6.9 77.43,57.78 74.23,57.78 73.43,56.98 70.63,56.98 65.83,61.78 65.83,63.38 64.63,64.58 IC3.6
N$42
  Top 0.508: C11.2 63.03,54.18 59.83,54.18 59.43,53.78 R28.2
  Bottom 0.508: L3.2 58.23,49.78 58.23,52.58 58.63,52.98 R28.2
N$43
  Top 0.508: 66.23,32.98 69.43,32.98 C12.2 | 66.23,32.98 65.83,32.98 T11.B | 66.23,32.98 66.23,44.18 59.83,50.58 57.03,50.58 56.23,49.78 48.23,49.78 L3.1
N$44
  Top 0.508: R29.1 59.43,30.98 61.03,30.98 63.03,32.98 T11.E 64.23,33.78 64.23,38.98 C13.2
N$45
  Bottom 0.305: 69.83,63.78 76.23,63.78 | 77.03,64.58 80.23,64.58
  Bottom 0.508: 69.83,63.78 66.23,67.38 64.63,67.38 IC3.5 | 76.23,63.78 77.03,64.58 | 80.23,64.58 84.23,60.58 84.23,59.38 85.03,58.58 IC6.10
N$46
  Top 0.508: IC6.8 79.83,61.38 81.83,63.38 81.83,79.38 80.23,80.98 17.83,80.98 14.63,77.78 14.63,62.18 13.43,60.98 13.43,58.98 15.03,57.38 15.43,57.38 25.43,47.38 25.43,45.78 35.03,36.18 40.63,36.18 42.63,34.18 47.83,34.18 R30.2
  Bottom 0.508: D3.C 73.03,58.98 75.83,58.98 77.43,60.58 IC6.8 | R30.2 49.03,34.18 53.03,34.18 60.63,41.78 64.23,41.78 C13.1
N$47
  Top 0.508: R32.2 87.83,16.18 87.83,23.78 87.43,24.18 87.43,44.98 93.03,50.58 D2.A
N$48
  Top 0.508: IC3.4 65.03,69.78 69.03,65.78 69.03,63.78 69.83,62.98 IC3.8
  Bottom 0.508: IC6.7 77.43,62.98 72.23,62.98 IC3.8
N$49
  Top 0.508: R35.2 59.43,36.18 61.03,36.18 R36.2 | C19.2 63.03,26.58 63.83,26.58 65.83,28.58 R37.1
  Bottom 0.508: R36.2 61.83,36.18 63.83,36.18 66.63,33.38 66.63,28.98 R37.1
N$52
  Top 0.508: IC6.15 87.43,70.98 89.83,70.98 J2.2
N$53
  Top 0.508: IC6.16 87.43,73.38 89.83,73.38 J2.1 93.03,72.98 94.23,71.78 94.23,65.01 91.43,62.3 91.43,60.58 J5.1
N$55
  Top 0.508: QG2.8 86.23,38.18 86.23,50.58 93.03,57.38 J5.2
N$63
  Bottom 0.406: 89.43,30.58 93.03,34.18
  Bottom 0.508: 89.43,30.58 89.43,29.38 R33.1 | 93.03,34.18 93.03,37.38 D1.A
N$64
  Bottom 0.305: 88.23,52.98 88.23,64.58
  Bottom 0.508: 88.23,52.98 76.23,40.98 76.23,36.58 76.63,36.18 76.63,31.38 78.63,29.38 R33.2 | 88.23,64.58 87.43,65.38 IC6.13
VCC
  Top 0.508: R37.2 67.03,18.98 69.83,18.98 70.63,19.78 C16.2 70.63,20.98 75.83,26.18 C18.2 | 54.23,20.18 56.63,20.18 C17.2 | 54.23,20.18 51.83,20.18 C15.2 51.03,20.18 51.03,25.38 C14.2 | 54.23,20.18 59.03,15.38 IC1.OUT | 88.63,68.18 89.83,68.18 J2.3 | 88.63,68.18 87.43,68.18 IC6.14 | 88.63,68.18 88.63,55.38 86.63,53.38 QG2.14 | IC3.14 72.63,78.18 75.43,78.18 77.43,80.18 79.83,80.18 81.03,78.98 81.03,72.58 79.83,71.38 IC6.4
  Bottom 0.305: 69.43,76.58 62.23,76.58
  Bottom 0.508: R37.2 66.23,18.18 63.03,18.18 59.83,14.98 IC1.OUT | 62.23,76.58 60.23,74.58 59.03,74.58 IC4.16 | 69.43,76.58 70.23,77.38 IC3.14 | IC6.4 79.83,70.58 83.03,70.58 85.03,68.58 IC6.14 | QG2.14 85.83,53.38 72.63,40.18 C27.+ 72.23,39.38 75.83,35.78 75.83,26.98 C18.2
